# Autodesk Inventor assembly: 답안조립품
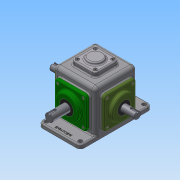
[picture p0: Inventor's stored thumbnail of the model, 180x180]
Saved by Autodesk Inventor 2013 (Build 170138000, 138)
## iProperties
Created: 2018-09
Part Number: 답안조립품
Document SubType Name: Assembly
Designer: Administrator
Mass: 3064.44 g
Surface Area: 2604.28 cm^2
Volume: 801.794 cm^3
Density: 3.82198 g/cm^3
Author: Administrator
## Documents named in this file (15)
- C:\Users\Administrator\Desktop\380908V1007\답안조립품.iam
- C:\Users\Administrator\Desktop\380908V1007\본체.ipt
- C:\Users\Administrator\Desktop\380908V1007\서브축.ipt
- C:\Users\Administrator\Desktop\380908V1007\메인베벨기어.ipt
- C:\Users\Administrator\Desktop\380908V1007\메인축.ipt
- C:\Users\Administrator\Desktop\380908V1007\키 4x4.ipt
- C:\Users\Administrator\Desktop\380908V1007\베어링 6204.ipt
- C:\Users\Administrator\Desktop\380908V1007\메인커버.ipt
- C:\Users\Administrator\Desktop\380908V1007\오일 실 20 35 8.ipt
- C:\Users\Administrator\Desktop\380908V1007\볼트 M4.ipt
- C:\Users\Administrator\Desktop\380908V1007\서브베벨기어.ipt
- C:\Users\Administrator\Desktop\380908V1007\베어링 6203.ipt
- C:\Users\Administrator\Desktop\380908V1007\서브커버.ipt
- C:\Users\Administrator\Desktop\380908V1007\오일 실 17 32 8.ipt
- C:\Users\Administrator\Desktop\380908V1007\상부커버.ipt
